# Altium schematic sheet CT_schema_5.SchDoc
size 266 x 267 mm
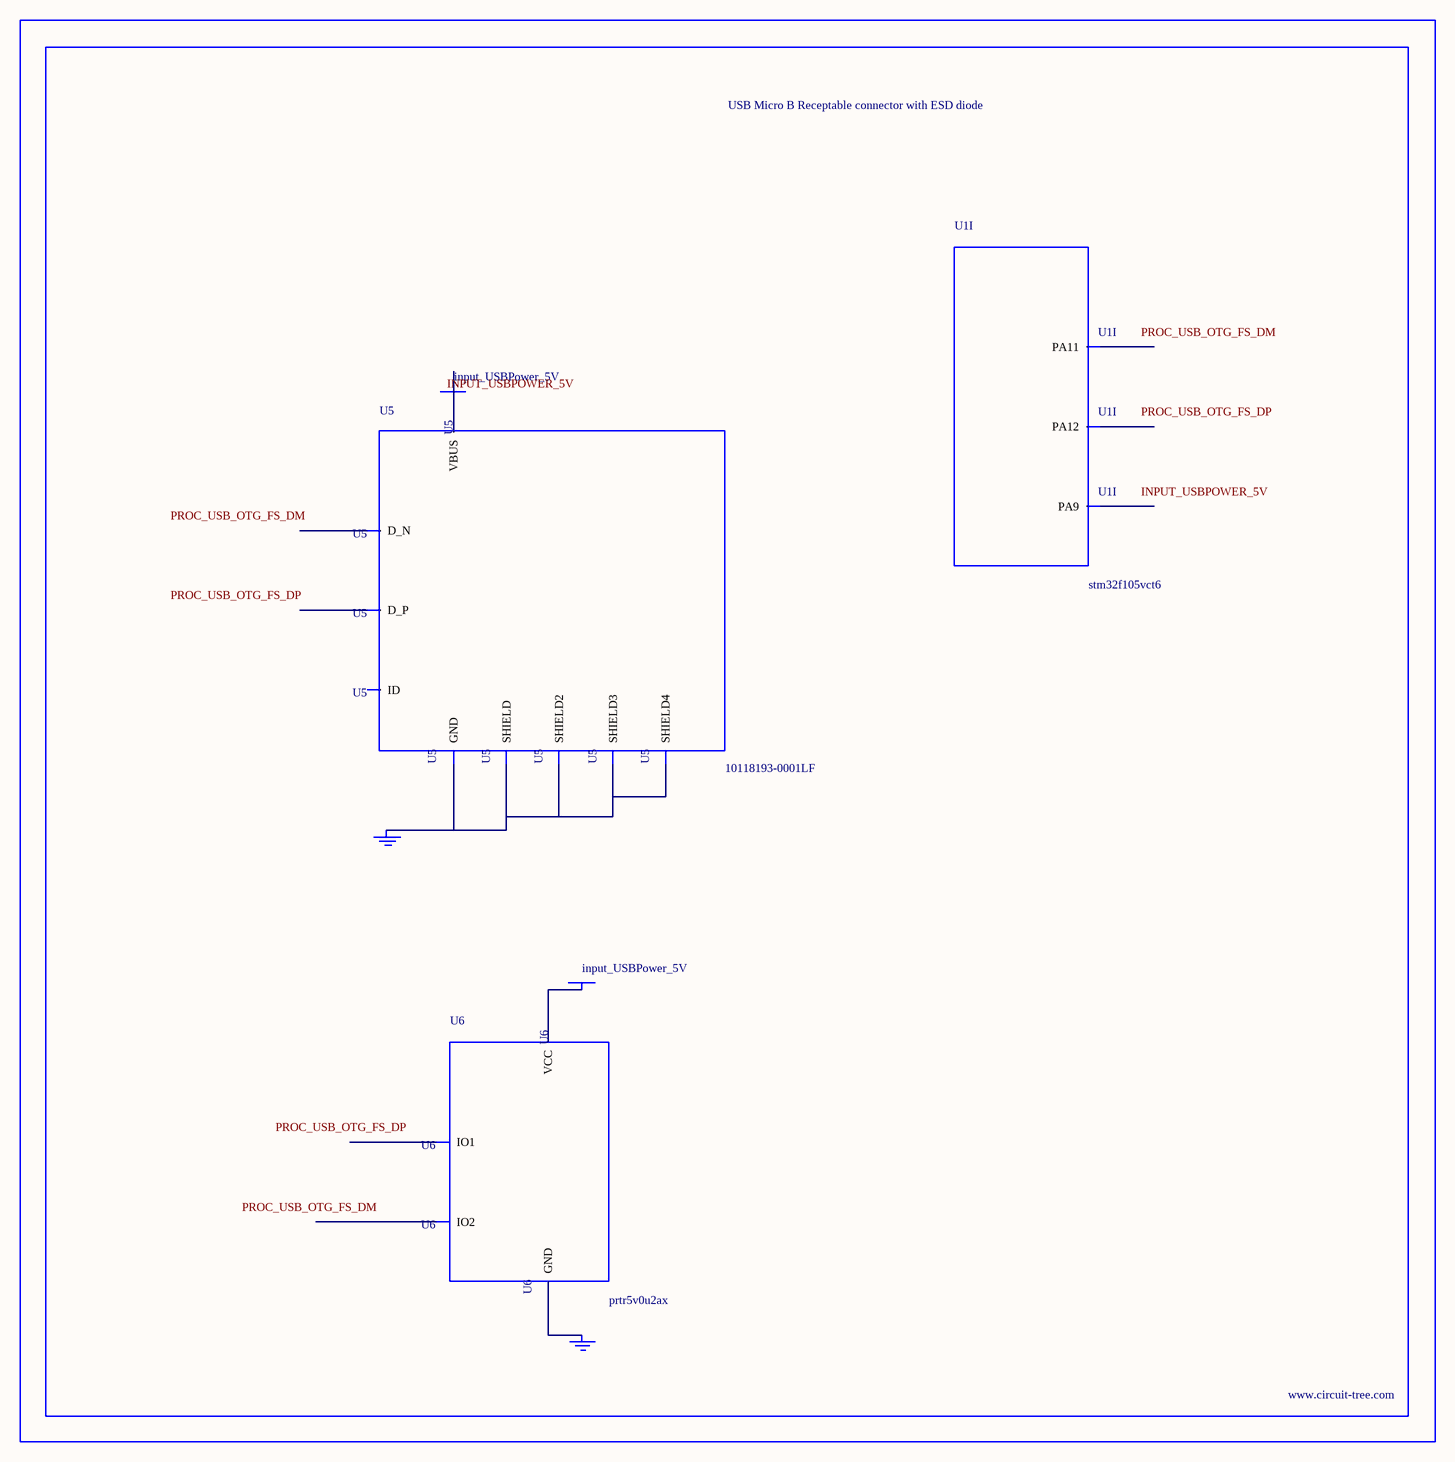
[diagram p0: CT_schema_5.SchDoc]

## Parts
BORDER4  (no value)
GND_INSTANCE_4_0  (no value)
GND_INSTANCE_4_1  (no value)
POWER_INSTANCE_4_0  input_USBPower_5V
POWER_INSTANCE_4_1  input_USBPower_5V
U1  stm32f105vct6  [LQFP100]  (part I of 10)
U5  10118193-0001LF  [FCI_10118193-0001LF]
U6  prtr5v0u2ax  [SOT143B]

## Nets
NetGND_INSTANCE_4_0_0: GND_INSTANCE_4_0.0(GND) U5.5(GND) U5.6(SHIELD) U5.7(SHIELD2) U5.8(SHIELD3) U5.9(SHIELD4)
NetGND_INSTANCE_4_1_0: GND_INSTANCE_4_1.0(GND) U6.1(GND)
NetPOWER_INSTANCE_4_0_0: POWER_INSTANCE_4_0.0(PWR) U5.1(VBUS)
NetPOWER_INSTANCE_4_1_0: POWER_INSTANCE_4_1.0(PWR) U6.4(VCC)

Not connected (* = marked no-connect by the designer): U1 68(PA9) 70(PA11) 71(PA12); U5 2(D_N) 3(D_P) 4(ID); U6 2(IO1) 3(IO2)

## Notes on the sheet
- Labels drawn without touching a wire or pin: INPUT_USBPOWER_5V, PROC_USB_OTG_FS_DM, PROC_USB_OTG_FS_DP

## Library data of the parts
BORDER4 = BORDER_PAGE4
GND_INSTANCE_4_0 GND_INSTANCE_4_1 = GND
POWER_INSTANCE_4_0 POWER_INSTANCE_4_1 = PWR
